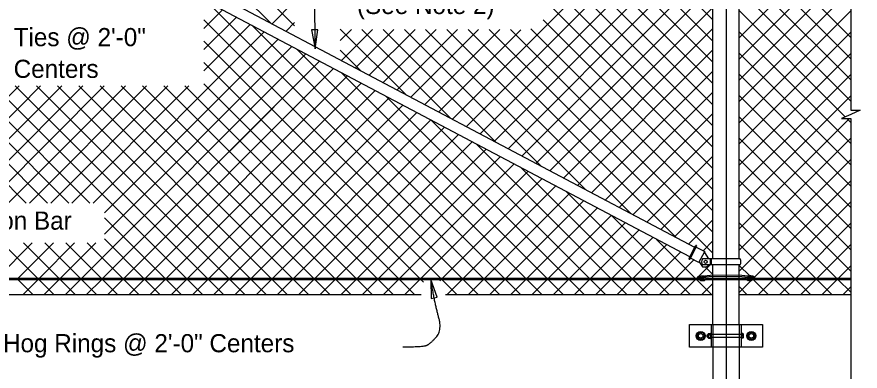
# Model space of a CAD drawing. Extents: x 0 to 72.1, y -15.2 to 30.1.
# Drawn here: x 6.75 to 16.12, y 18.43 to 22.36 of the extents above; entities that cross this region are included whole.
import ezdxf

# ---------------------------------------------------------------- set-up
doc = ezdxf.new("R2010")
doc.units = 0
for name, color, linetype in [('AdhocPoint_dp', 7, 'Continuous'), ('Border', 7, 'Continuous'), ('Patterning', 7, 'Continuous'), ('PlotBorder_dp', 7, 'Continuous'), ('SheetBorder_dp', 7, 'Continuous'), ('SheetLines_dp', 7, 'Continuous'), ('TextMisc', 7, 'Continuous')]:
    doc.layers.add(name, color=color, linetype=linetype)

msp = doc.modelspace()

# ---------------------------------------------------------------- linework, layer by layer
at = {"layer": 'AdhocPoint_dp'}
for p, q in [((4.7769, 19.2783), (11.2453, 19.2783)), ((11.5141, 19.2783), (14.4852, 19.2783)), ((14.7769, 19.2783), (16.018, 19.2783))]:
    msp.add_line(p, q, dxfattribs=at)
at = {"layer": 'Border'}
for p, q in [((14.4852, 19.4597), (14.7769, 19.4597)), ((14.4852, 19.445), (14.7769, 19.445)), ((14.4852, 18.9432), (14.4852, 18.6932)), ((14.7769, 18.9432), (14.7769, 18.6932)), ((14.7978, 18.8328), (14.4329, 18.8328)), ((14.4329, 18.8029), (14.7978, 18.8029))]:
    msp.add_line(p, q, dxfattribs=at)
at = {"layer": 'Patterning'}
for p, q in [((6.7659, 25.0969), (9.5731, 22.2897)), ((7.0016, 25.0969), (9.8384, 22.2601)), ((10.5372, 25.0969), (14.4852, 21.1488)), ((10.7729, 25.0969), (14.4852, 21.3845)), ((11.0086, 25.0969), (14.4852, 21.6202)), ((11.2443, 25.0969), (14.4852, 21.8559)), ((11.48, 25.0969), (14.4852, 22.0916)), ((11.7157, 25.0969), (14.4852, 22.3273)), ((11.5927, 21.2224), (14.4852, 24.1149)), ((11.7469, 21.1409), (14.4852, 23.8792)), ((11.9012, 21.0594), (14.4852, 23.6435)), ((12.0554, 20.9779), (14.4852, 23.4078)), ((14.7769, 23.3718), (16.018, 22.1307)), ((14.7769, 22.1276), (16.018, 23.3687)), ((4.9019, 23.1897), (8.6318, 19.4597)), ((12.2096, 20.8964), (14.4852, 23.1721)), ((14.7769, 23.1361), (16.018, 21.895)), ((14.7769, 21.8919), (16.018, 23.133)), ((4.9019, 22.954), (7.5632, 20.2926)), ((12.3638, 20.815), (14.4852, 22.9364)), ((14.7769, 22.9004), (16.018, 21.6593)), ((14.7769, 21.6562), (16.018, 22.8973)), ((4.9019, 22.7183), (7.3275, 20.2926)), ((12.518, 20.7335), (14.4852, 22.7007)), ((12.6609, 22.7374), (14.4852, 20.9131)), ((14.7769, 22.6647), (16.018, 21.4236)), ((14.7769, 21.4205), (16.018, 22.6616)), ((8.861, 22.5304), (11.9317, 19.4597)), ((9.588, 22.2818), (9.8384, 22.5323)), ((12.6374, 22.5252), (14.4852, 20.6774)), ((4.9019, 22.4826), (7.0918, 20.2926)), ((8.8306, 22.2315), (9.0367, 22.4376)), ((12.6722, 20.652), (14.4852, 22.465)), ((14.7769, 22.429), (15.9555, 21.2505)), ((14.7769, 21.1848), (16.018, 22.4259)), ((8.8306, 21.9958), (9.1909, 22.3561)), ((8.8306, 22.3252), (11.696, 19.4597)), ((12.5993, 22.3277), (14.4852, 20.4417)), ((4.9036, 22.2451), (6.8561, 20.2926)), ((8.8306, 21.7601), (9.3451, 22.2746)), ((9.3609, 22.2662), (12.1674, 19.4597)), ((9.7422, 22.2003), (9.8384, 22.2965)), ((10.3448, 22.2251), (11.0727, 21.4972)), ((10.3448, 22.0958), (10.4684, 22.2194)), ((10.3591, 21.8744), (10.7041, 22.2194)), ((10.5133, 21.7929), (10.9398, 22.2194)), ((10.5862, 22.2194), (11.5725, 21.2331)), ((10.6675, 21.7114), (11.1755, 22.2194)), ((10.6675, 21.7114), (11.1755, 22.2194)), ((10.8217, 21.6299), (11.4112, 22.2194)), ((10.8219, 22.2194), (12.0724, 20.9689)), ((10.9759, 21.5484), (11.6469, 22.2194)), ((11.0576, 22.2194), (12.5722, 20.7048)), ((11.1301, 21.4669), (11.8826, 22.2194)), ((11.2843, 21.3854), (12.1183, 22.2194)), ((11.2933, 22.2194), (13.0721, 20.4406)), ((11.4385, 21.3039), (12.3501, 22.2155)), ((11.529, 22.2194), (13.5719, 20.1765)), ((11.7647, 22.2194), (14.0718, 19.9123)), ((12.0004, 22.2194), (14.4852, 19.7346)), ((12.2361, 22.2194), (14.4852, 19.9703)), ((12.4639, 22.2273), (14.4852, 20.206)), ((12.8264, 20.5705), (14.4852, 22.2293)), ((7.5988, 20.2926), (9.4993, 22.1931)), ((14.7769, 22.1933), (16.018, 20.9522)), ((14.7769, 20.9491), (16.018, 22.1902)), ((7.7263, 20.1844), (9.6535, 22.1116)), ((7.7263, 19.9487), (9.8077, 22.0301)), ((8.8306, 22.0895), (11.4603, 19.4597)), ((9.1077, 21.3301), (9.8077, 22.0301)), ((7.473, 19.4597), (9.9619, 21.9486)), ((9.1077, 21.0944), (9.9619, 21.9486)), ((9.8607, 22.0021), (12.4031, 19.4597)), ((10.3448, 21.9894), (10.5728, 21.7614)), ((12.9806, 20.489), (14.4852, 21.9936)), ((14.7769, 21.9576), (16.018, 20.7165)), ((14.7769, 20.7134), (16.018, 21.9545)), ((7.7087, 19.4597), (10.1161, 21.8671)), ((8.8306, 21.8537), (11.2246, 19.4597)), ((9.1077, 20.8587), (10.1161, 21.8671)), ((7.9444, 19.4597), (10.2703, 21.7856)), ((10.3606, 21.738), (12.6388, 19.4597)), ((13.1348, 20.4075), (14.4852, 21.7579)), ((8.1801, 19.4597), (10.4245, 21.7041)), ((14.7769, 21.7219), (16.018, 20.4808)), ((14.7769, 20.4777), (16.018, 21.7188)), ((5.7434, 20.5585), (6.7787, 21.5938)), ((5.8347, 20.4141), (7.0144, 21.5938)), ((5.9489, 20.2926), (7.2501, 21.5938)), ((6.1846, 20.2926), (7.4858, 21.5938)), ((6.4203, 20.2926), (7.7215, 21.5938)), ((6.656, 20.2926), (7.9572, 21.5938)), ((6.7335, 21.5938), (8.8675, 19.4597)), ((6.8917, 20.2926), (8.1929, 21.5938)), ((6.9692, 21.5938), (9.1033, 19.4597)), ((7.1274, 20.2926), (8.4286, 21.5938)), ((7.2049, 21.5938), (9.339, 19.4597)), ((7.3631, 20.2926), (8.6643, 21.5938)), ((7.4406, 21.5938), (9.5747, 19.4597)), ((7.6763, 21.5938), (9.8104, 19.4597)), ((7.912, 21.5938), (10.0461, 19.4597)), ((8.1477, 21.5938), (10.2818, 19.4597)), ((8.3834, 21.5938), (10.5175, 19.4597)), ((8.4158, 19.4597), (10.5788, 21.6227)), ((8.6191, 21.5938), (10.7532, 19.4597)), ((8.8306, 21.618), (10.9889, 19.4597)), ((8.6515, 19.4597), (10.733, 21.5412)), ((8.8872, 19.4597), (10.8872, 21.4597)), ((10.8604, 21.4738), (12.8745, 19.4597)), ((13.289, 20.326), (14.4852, 21.5222)), ((14.7769, 21.4862), (16.018, 20.2451)), ((14.7769, 20.242), (16.018, 21.4831)), ((9.1229, 19.4597), (11.0414, 21.3782)), ((9.3586, 19.4597), (11.1956, 21.2967)), ((13.4432, 20.2445), (14.4852, 21.2865)), ((9.5943, 19.4597), (11.3498, 21.2152)), ((11.3602, 21.2097), (13.1102, 19.4597)), ((14.7769, 21.2505), (16.018, 20.0094)), ((14.7769, 20.0063), (16.0033, 21.2327)), ((15.9733, 21.2327), (16.018, 21.1879)), ((9.83, 19.4597), (11.504, 21.1337)), ((10.0657, 19.4597), (11.6582, 21.0522)), ((13.5975, 20.163), (14.4852, 21.0508)), ((14.7769, 21.0148), (16.018, 19.7737)), ((14.7769, 19.7706), (16.018, 21.0117)), ((10.3015, 19.4597), (11.8124, 20.9707)), ((11.8601, 20.9455), (13.3459, 19.4597)), ((10.5372, 19.4597), (11.9667, 20.8892)), ((10.655, 19.3419), (12.1209, 20.8077)), ((13.7517, 20.0815), (14.4852, 20.8151)), ((11.0086, 19.4597), (12.2751, 20.7262)), ((14.7769, 20.7791), (16.018, 19.538)), ((14.7769, 19.5349), (16.018, 20.776)), ((11.2443, 19.4597), (12.4293, 20.6448)), ((12.3599, 20.6814), (13.5816, 19.4597)), ((11.48, 19.4597), (12.5835, 20.5633)), ((13.9059, 20), (14.4852, 20.5794)), ((14.7769, 20.5434), (15.8606, 19.4597)), ((14.9463, 19.4686), (16.018, 20.5403)), ((11.7157, 19.4597), (12.7377, 20.4818)), ((11.9514, 19.4597), (12.8919, 20.4003)), ((12.8598, 20.4173), (13.8173, 19.4597)), ((14.0601, 19.9185), (14.4852, 20.3437)), ((12.1871, 19.4597), (13.0461, 20.3188)), ((14.7769, 20.3077), (15.6249, 19.4597)), ((15.1732, 19.4597), (16.018, 20.3046)), ((12.4228, 19.4597), (13.2003, 20.2373)), ((12.6585, 19.4597), (13.3545, 20.1558)), ((13.3596, 20.1531), (14.053, 19.4597)), ((7.7263, 20.1296), (8.3961, 19.4597)), ((12.8942, 19.4597), (13.5088, 20.0743)), ((14.2143, 19.837), (14.4852, 20.108)), ((14.7769, 20.072), (15.3892, 19.4597)), ((15.4089, 19.4597), (16.018, 20.0689)), ((13.1299, 19.4597), (13.663, 19.9928)), ((7.7263, 19.8938), (8.1604, 19.4597)), ((13.3656, 19.4597), (13.8172, 19.9113)), ((13.8594, 19.889), (14.2887, 19.4597)), ((14.376, 19.7631), (14.4852, 19.8723)), ((6.5302, 19.4597), (6.9219, 19.8514)), ((6.5902, 19.8514), (6.9819, 19.4597)), ((6.7659, 19.4597), (7.1576, 19.8514)), ((6.8259, 19.8514), (7.2176, 19.4597)), ((7.0016, 19.4597), (7.3933, 19.8514)), ((7.0616, 19.8514), (7.4533, 19.4597)), ((7.2373, 19.4597), (7.629, 19.8514)), ((7.2973, 19.8514), (7.689, 19.4597)), ((7.533, 19.8514), (7.9247, 19.4597)), ((13.6013, 19.4597), (13.9714, 19.8298)), ((14.7769, 19.8363), (15.1535, 19.4597)), ((15.6446, 19.4597), (16.018, 19.8332)), ((13.837, 19.4597), (14.1256, 19.7483)), ((14.0727, 19.4597), (14.2751, 19.6622)), ((14.3243, 19.4757), (14.4539, 19.6052)), ((14.3996, 19.5846), (14.4852, 19.4989)), ((14.7769, 19.6006), (14.8943, 19.4832)), ((15.8803, 19.4597), (16.018, 19.5974)), ((6.761, 19.445), (6.9276, 19.2783)), ((6.8202, 19.2783), (6.9869, 19.445)), ((6.9967, 19.445), (7.1633, 19.2783)), ((7.0559, 19.2783), (7.2226, 19.445)), ((7.2324, 19.445), (7.3991, 19.2783)), ((7.2916, 19.2783), (7.4583, 19.445)), ((7.4681, 19.445), (7.6348, 19.2783)), ((7.5273, 19.2783), (7.694, 19.445)), ((7.7038, 19.445), (7.8705, 19.2783)), ((7.763, 19.2783), (7.9297, 19.445)), ((7.9395, 19.445), (8.1062, 19.2783)), ((7.9987, 19.2783), (8.1654, 19.445)), ((8.1752, 19.445), (8.3419, 19.2783)), ((8.2344, 19.2783), (8.4011, 19.445)), ((8.4109, 19.445), (8.5776, 19.2783)), ((8.4701, 19.2783), (8.6368, 19.445)), ((8.6466, 19.445), (8.8133, 19.2783)), ((8.7058, 19.2783), (8.8725, 19.445)), ((8.8823, 19.445), (9.049, 19.2783)), ((8.9415, 19.2783), (9.1082, 19.445)), ((9.118, 19.445), (9.2847, 19.2783)), ((9.1772, 19.2783), (9.3439, 19.445)), ((9.3537, 19.445), (9.5204, 19.2783)), ((9.4129, 19.2783), (9.5796, 19.445)), ((9.5894, 19.445), (9.7561, 19.2783)), ((9.6486, 19.2783), (9.8153, 19.445)), ((9.8251, 19.445), (9.9918, 19.2783)), ((9.8843, 19.2783), (10.051, 19.445)), ((10.0608, 19.445), (10.2275, 19.2783)), ((10.12, 19.2783), (10.2867, 19.445)), ((10.2965, 19.445), (10.4632, 19.2783)), ((10.3557, 19.2783), (10.5224, 19.445)), ((10.5322, 19.445), (10.6989, 19.2783)), ((10.5914, 19.2783), (10.7581, 19.445)), ((10.7679, 19.445), (10.9346, 19.2783)), ((10.8271, 19.2783), (10.9938, 19.445)), ((11.0036, 19.445), (11.1703, 19.2783)), ((11.0628, 19.2783), (11.2295, 19.445)), ((11.2393, 19.445), (11.2705, 19.4138)), ((11.4511, 19.4309), (11.4652, 19.445)), ((11.475, 19.445), (11.6417, 19.2783)), ((11.5342, 19.2783), (11.7009, 19.445)), ((11.7107, 19.445), (11.8774, 19.2783)), ((11.7699, 19.2783), (11.9366, 19.445)), ((11.9464, 19.445), (12.1131, 19.2783)), ((12.0057, 19.2783), (12.1723, 19.445)), ((12.1821, 19.445), (12.3488, 19.2783)), ((12.2414, 19.2783), (12.408, 19.445)), ((12.4178, 19.445), (12.5845, 19.2783)), ((12.4771, 19.2783), (12.6437, 19.445)), ((12.6535, 19.445), (12.8202, 19.2783)), ((12.7128, 19.2783), (12.8794, 19.445)), ((12.8892, 19.445), (13.0559, 19.2783)), ((12.9485, 19.2783), (13.1151, 19.445)), ((13.1249, 19.445), (13.2916, 19.2783)), ((13.1842, 19.2783), (13.3508, 19.445)), ((13.3606, 19.445), (13.5273, 19.2783)), ((13.4199, 19.2783), (13.5865, 19.445)), ((13.5963, 19.445), (13.763, 19.2783)), ((13.6556, 19.2783), (13.8222, 19.445)), ((13.832, 19.445), (13.9987, 19.2783)), ((13.8913, 19.2783), (14.0579, 19.445)), ((14.0677, 19.445), (14.2344, 19.2783)), ((14.127, 19.2783), (14.2936, 19.445)), ((14.3035, 19.445), (14.4701, 19.2783)), ((14.3084, 19.4597), (14.312, 19.4633)), ((14.3627, 19.2783), (14.4852, 19.4009)), ((14.7769, 19.2992), (14.9152, 19.4375)), ((14.9325, 19.445), (15.0992, 19.2783)), ((14.9918, 19.2783), (15.1584, 19.445)), ((15.1682, 19.445), (15.3349, 19.2783)), ((15.2275, 19.2783), (15.3941, 19.445)), ((15.4039, 19.445), (15.5706, 19.2783)), ((15.4632, 19.2783), (15.6298, 19.445)), ((15.6396, 19.445), (15.8063, 19.2783)), ((15.6989, 19.2783), (15.8655, 19.445)), ((15.8753, 19.445), (16.018, 19.3023)), ((14.7802, 19.3616), (14.8635, 19.2783)), ((15.9346, 19.2783), (16.018, 19.3617)), ((14.4235, 18.8113), (14.4235, 18.8234)), ((14.4292, 18.8113), (14.4292, 18.8234))]:
    msp.add_line(p, q, dxfattribs=at)
at = {"layer": 'PlotBorder_dp'}
for points in [[(16.018, 25.2804), (16.018, 23.3241), (16.1214, 23.3241), (16.018, 23.2791), (15.9147, 23.2341), (16.018, 23.2341), (16.018, 22.3405)], [(16.018, 22.3405), (16.018, 21.3227), (16.1214, 21.3227), (16.018, 21.2777), (15.9147, 21.2327), (16.018, 21.2327), (16.018, 19.0284)], [(16.018, 19.2784), (16.018, 17.4276), (16.1214, 17.4276), (16.018, 17.3826), (15.9147, 17.3376), (16.018, 17.3376), (16.018, 14.9877)]]:
    msp.add_lwpolyline(points, dxfattribs=at)
for points in [[(10.0663, 22.0067), (10.0975, 22.2156), (10.027, 22.2142)], [(11.352, 19.445), (11.3536, 19.2338), (11.4231, 19.2461)]]:
    msp.add_lwpolyline(points, close=True, dxfattribs=at)
for points in [[(6.6335, 22.1348), (6.5026, 22.1207), (6.3196, 22.188), (6.3281, 22.5146), (6.961, 23.5344)], [(10.4442, 22.859), (10.1746, 22.8671), (10.0565, 22.7087), (10.0536, 22.5875), (10.0582, 22.4197), (10.0663, 22.0067)], [(11.0408, 18.6981), (11.2636, 18.6945), (11.3485, 18.7335), (11.4794, 18.8822), (11.3945, 19.1796), (11.352, 19.4449)]]:
    msp.add_open_spline(points, degree=2, dxfattribs=at)
at = {"layer": 'SheetBorder_dp'}
msp.add_line((14.631, 27.059), (14.631, 16.8122), dxfattribs=at)
at = {"layer": 'TextMisc'}
for p, q in [((14.4852, 19.6731), (14.4852, 25.3183)), ((14.7769, 19.6731), (14.7769, 25.3183)), ((14.2837, 19.8004), (5.0341, 24.6884)), ((14.2277, 19.6944), (4.978, 24.5823)), ((14.2202, 19.6802), (14.2926, 19.8173)), ((14.232, 19.6739), (14.3045, 19.811)), ((14.3003, 19.8031), (14.3946, 19.7533)), ((14.3309, 19.6327), (14.2366, 19.6826)), ((14.3309, 19.6327), (14.3946, 19.7533)), ((14.3904, 19.7453), (14.4373, 19.6735)), ((14.3344, 19.6393), (14.3691, 19.5861)), ((14.7882, 19.6731), (14.3685, 19.6731)), ((14.7881, 19.6053), (14.3685, 19.6053)), ((14.4509, 19.6668), (14.4744, 19.6668)), ((14.4509, 19.657), (14.4744, 19.657)), ((14.4509, 19.6453), (14.4744, 19.6453)), ((14.4509, 19.6335), (14.4744, 19.6335)), ((14.4509, 19.6227), (14.4744, 19.6227)), ((14.4509, 19.6131), (14.4744, 19.6131)), ((14.4852, 18.9432), (14.4852, 19.6052)), ((14.7769, 18.9432), (14.7769, 19.6052)), ((14.4852, 19.4923), (14.3904, 19.4812)), ((14.4852, 19.4923), (14.7764, 19.494)), ((14.7764, 19.494), (14.8707, 19.4829)), ((4.939, 19.445), (14.3367, 19.445)), ((4.9403, 19.4597), (14.3101, 19.4597)), ((14.32, 19.4597), (14.3332, 19.4597)), ((14.4852, 19.4778), (14.3926, 19.4683)), ((14.4016, 19.445), (14.4852, 19.445)), ((14.4031, 19.4597), (14.4852, 19.4597)), ((14.4852, 19.4778), (14.7764, 19.4795)), ((14.7764, 19.4795), (14.8685, 19.4701)), ((14.7769, 19.4597), (14.8573, 19.4597)), ((14.7769, 19.445), (14.86, 19.445)), ((14.9219, 19.445), (16.018, 19.445)), ((14.9276, 19.4597), (14.9429, 19.4597)), ((14.9514, 19.4597), (16.018, 19.4597)), ((14.2251, 18.9432), (15.0371, 18.9432)), ((14.2251, 18.6932), (14.2251, 18.9432)), ((14.4644, 18.9432), (14.4644, 18.6932)), ((14.7977, 18.9432), (14.7977, 18.6932)), ((15.0371, 18.9432), (15.0371, 18.6932)), ((14.4329, 18.8361), (14.4329, 18.8004)), ((14.4378, 18.8442), (14.4579, 18.8442)), ((14.4579, 18.8485), (14.4579, 18.7879)), ((14.4579, 18.8485), (14.4644, 18.8485)), ((14.4579, 18.8442), (14.4579, 18.7922)), ((14.804, 18.8485), (14.798, 18.8485)), ((14.804, 18.8485), (14.804, 18.7879)), ((14.8187, 18.8442), (14.804, 18.8442)), ((14.8238, 18.7988), (14.8238, 18.8377)), ((14.4207, 18.8262), (14.4263, 18.8328)), ((14.4207, 18.8085), (14.4207, 18.8262)), ((14.4207, 18.8085), (14.4263, 18.8029)), ((14.4263, 18.8328), (14.4329, 18.8328)), ((14.4263, 18.8029), (14.4263, 18.8328)), ((14.4263, 18.8029), (14.4329, 18.8029)), ((14.4376, 18.8312), (14.4579, 18.8312)), ((14.4376, 18.8053), (14.4579, 18.8053)), ((14.4379, 18.7922), (14.4579, 18.7922)), ((14.4579, 18.7879), (14.4644, 18.7879)), ((14.804, 18.7879), (14.798, 18.7879)), ((14.8189, 18.8312), (14.804, 18.8312)), ((14.8189, 18.8052), (14.804, 18.8052)), ((14.8187, 18.7922), (14.804, 18.7922)), ((15.0371, 18.6932), (14.2251, 18.6932)), ((14.4852, 18.6932), (14.4852, 17.4432)), ((14.7769, 18.6932), (14.7769, 17.4432))]:
    msp.add_line(p, q, dxfattribs=at)
for points in [[(14.3284, 18.8557), (14.3718, 18.8557), (14.3934, 18.8182), (14.3718, 18.7807), (14.3284, 18.7807), (14.3067, 18.8182)], [(14.8904, 18.8557), (14.9337, 18.8557), (14.9554, 18.8182), (14.9337, 18.7807), (14.8904, 18.7807), (14.8687, 18.8182)]]:
    msp.add_lwpolyline(points, close=True, dxfattribs=at)
for centre, radius in [((14.3501, 18.8182), 0.05), ((14.3501, 18.8182), 0.025), ((14.9121, 18.8182), 0.05), ((14.9121, 18.8182), 0.025)]:
    msp.add_circle(centre, radius, dxfattribs=at)
for centre, radius, start, end in [((14.2987, 19.8143), 0.00673, 332.14902, 152.14902), ((14.2262, 19.6771), 0.00673, 152.14902, 332.14902), ((14.4394, 18.8377), 0.00674, 104.48908, 254.18889), ((14.817, 18.8376), 0.00673, 285.7823, 75.54039), ((14.4523, 18.8182), 0.0196, 138.62797, 221.37203), ((14.4394, 18.7987), 0.00673, 105.7823, 255.54039), ((14.817, 18.7987), 0.00674, 284.48908, 74.18889), ((14.8041, 18.8182), 0.0196, 318.62797, 41.37203)]:
    msp.add_arc(centre, radius, start, end, dxfattribs=at)
for centre, major_axis, ratio, start_param, end_param in [((14.4377, 19.6394), (-0.0776, 0), 0.957868, 5.810211, 6.75616), ((14.3857, 19.6544), (0.0647, -0.0342), 0.957868, 4.95193, 6.011789), ((14.7191, 19.6393), (0.0776, 0), 0.957868, 5.807767, 6.754779), ((14.3443, 19.4455), (0.0373, 0), 0.957868, 1.486836, 3.108042), ((14.3654, 19.4058), (-0.0724, 0), 0.957868, 5.162149, 5.652106), ((14.358, 19.4574), (-0.0249, 0), 0.957868, 6.009018, 7.089857), ((14.3568, 19.4599), (0.023, 0), 0.957868, 1.29026, 2.970541), ((14.3593, 19.4534), (0.0231, 0), 0.957868, 3.779554, 4.879821), ((14.3756, 19.4546), (0.0295, 0), 0.957868, 1.220941, 4.039556), ((14.389, 19.4563), (-0.0303, -0.0108), 0.724765, 4.35367, 6.324556), ((14.3654, 19.4477), (0.0206, -0.0021), 0.798607, 4.32653, 5.220153), ((14.3789, 19.4477), (0.0206, -0.0021), 0.798607, 3.333154, 5.220153), ((14.3857, 19.4523), (-0.0139, 0), 0.957868, 5.22362, 6.905413), ((14.3801, 19.4499), (-0.00795, 0), 0.957868, 6.140374, 9.314262), ((14.3941, 19.4434), (-0.0259, 0), 0.957868, 4.777514, 5.62749), ((14.3784, 19.4557), (0.0119, 0), 0.957868, 5.725876, 7.416677), ((14.3715, 19.4665), (0.0391, 0), 0.957868, 5.082588, 5.41974), ((14.3784, 19.4557), (0.0119, 0), 0.957868, 5.639684, 5.723117), ((14.3786, 19.4544), (0.0251, 0), 0.957868, 5.531357, 6.227833), ((14.3786, 19.4544), (0.0251, 0), 0.957868, 0.407687, 0.609214), ((14.8821, 19.4562), (-0.0251, 0), 0.957868, 0.055352, 0.751829), ((14.8821, 19.4562), (-0.0251, 0), 0.957868, 5.673972, 5.875498), ((14.8892, 19.4683), (-0.0391, 0), 0.957868, 0.863445, 1.200597), ((14.8717, 19.4581), (0.0303, -0.0108), 0.724765, 6.241815, 8.212701), ((14.8666, 19.4452), (0.0259, 0), 0.957868, 0.655696, 1.505671), ((14.8823, 19.4575), (-0.0119, 0), 0.957868, 5.149694, 6.840495), ((14.8823, 19.4575), (-0.0119, 0), 0.957868, 0.560069, 0.643501), ((14.8807, 19.4517), (0.00795, 0), 0.957868, 3.252108, 6.425997), ((14.8818, 19.4495), (-0.0206, -0.0021), 0.798607, 1.063032, 2.950031), ((14.8851, 19.4563), (-0.0295, 0), 0.957868, 2.243629, 5.062245), ((14.875, 19.454), (0.0139, 0), 0.957868, 5.660958, 7.342751), ((14.8953, 19.4495), (-0.0206, -0.0021), 0.798607, 1.063032, 1.956656), ((14.9039, 19.4617), (-0.023, 0), 0.957868, 3.312645, 4.992926), ((14.9014, 19.4552), (-0.0231, 0), 0.957868, 1.403365, 2.503632), ((14.9164, 19.4472), (-0.0373, 0), 0.957868, 3.175144, 4.79635), ((14.9028, 19.4592), (0.0249, 0), 0.957868, 5.476514, 6.557353), ((14.8953, 19.4075), (0.0724, 0), 0.957868, 0.631079, 1.121037)]:
    msp.add_ellipse(centre, major_axis=major_axis, ratio=ratio, start_param=start_param, end_param=end_param, dxfattribs=at)
msp.add_ellipse((14.4044, 19.6398), major_axis=(0.0178, 0), ratio=0.957868, dxfattribs=at)

# ---------------------------------------------------------------- texts
at = {"layer": 'PlotBorder_dp'}
for s, p in [('Ties @ 2\'-0" ', (6.7159, 22.0343)), ('Centers', (6.7159, 21.6823))]:
    msp.add_text(s, height=0.2016, dxfattribs=at).set_placement(p)
at = {"layer": 'SheetLines_dp'}
for s, p in [('(See Note 2)', (10.5307, 22.3913)), ('Tension Bar', (5.908, 19.9971)), ('Hog Rings @ 2\'-0" Centers', (6.5976, 18.6361))]:
    msp.add_text(s, height=0.2016, dxfattribs=at).set_placement(p)

doc.saveas('drawing.dxf')
